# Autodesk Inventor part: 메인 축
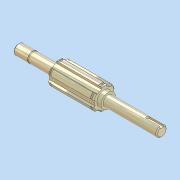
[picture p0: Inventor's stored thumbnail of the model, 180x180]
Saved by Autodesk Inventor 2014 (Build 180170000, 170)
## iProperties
Created: 2012-05
Part Number: 메인 축
Document SubType Name: 모델링
Designer: SeoGD™
Mass: 21.4462 g
Surface Area: 72.5109 cm^2
Volume: 21.4462 cm^3
Density: 1 g/cm^3
Material: 일반
Appearance: 기본값
변환 표준: STEP AP214IS
파일 이름: C:\Users\SeoGD\Desktop\?쒗뿕\硫붿씤 異?.stp
전처리기: Build: 253, Release: 2010 SP1 - Date: Wed 07/29/2009
전송 단위: 밀리미터
불확실성: 0.01
Author: SeoGD™
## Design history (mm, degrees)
sketch "스케치1"
  geometry: L1 (-69.5, 0)-(69.5, 0); L2 (69.5, 0)-(69.5, 5); L3 (69.5, 5)-(55.5, 5); L4 (55.5, 5)-(55.5, 4.8); L5 (55.5, 4.8)-(54.35, 4.8); L6 (54.35, 4.8)-(54.35, 5); L7 (54.35, 5)-(30.5, 5); L8 (30.5, 5)-(30.5, 9); L9 (30.5, 9)-(-13.5, 9); L10 (-13.5, 9)-(-13.5, 7); L11 (-13.5, 7)-(-17.5, 7); L12 (-17.5, 7)-(-17.5, 5); L13 (-17.5, 5)-(-69.5, 5); L14 (-69.5, 5)-(-69.5, 0); 2 further points
  constraints: 28 end point, 9 parallel, 4 collinear, 2 perpendicular, 1 coincident, 1 horizontal, 1 midpoint
  dimensions: "d2" = 1.15 distance between parallel lines of L6 L4; "d3" = 10 diameter of L3 L1; "d4" = 9.6 diameter of L5 L1; "d6" = 44 distance between parallel lines of L10 L8; "d7" = 4 distance between parallel lines of L12 L10; "d8" = 14 diameter of L11 L1; "d9" = 18 diameter of L9 L1; "d33" = 52 distance from line of L12.end L14; "d37" = 39 distance between parallel lines of L8 L2; "d38" = 14 distance between parallel lines of L2 L4
revolve "회전1" sketch "스케치1" stored, may be unused: angle "d10" = 90 deg
sketch "스케치2"
  geometry: L1 (2.5, 10.712)-(2.5, 8.646); L2 (-2.5, 10.712)-(-2.5, 8.646); A1 r 9 centre (0, 0) between (2.5, 8.646) and (-2.5, 8.646) reference; A2 r 11 centre (0, 0) between (2.5, 10.712) and (-2.5, 10.712); 1 further point
  constraints: 4 end point, 4 point on circle, 2 parallel, 1 centre point, 1 coincident, 1 vertical
  dimensions: "d11" = 22 diameter of A2; "d12" = 5 distance between parallel lines of L1 L2
extrude "돌출1" join sketch "스케치2" stored distance "d13" = 10; taper "d14" = 0 deg
chamfer "모따기1" distance "d15" = 1; stored, may be unused: second distance "d16" = 2, angle "d17" = 45 deg
node "작업 평면1"
node "작업 평면2"
sketch "스케치3"
  geometry: L1 (2.5, 10.712)-(2.5, 10.198); L2 (-2.5, 10.712)-(-2.5, 10.198); A1 r 11 centre (0, 0) between (2.5, 10.712) and (-2.5, 10.712) reference; A2 r 10.5 centre (0, 0) between (2.5, 10.198) and (-2.5, 10.198); 1 further point
  constraints: 4 end point, 2 point on circle, 1 centre point, 1 coincident, 1 parallel, 1 vertical
  dimensions: "d19" = 21 diameter of A2
extrude "돌출2" cut sketch "스케치3" distance "d20" = 1.35; taper "d21" = 0 deg
node "작업 평면3"
sketch "스케치4"
  geometry: L1 (-26, -5)-(-26, 5) reference; L2 (-26, 1.5)-(-12.5, 1.5); L3 (-12.5, -1.5)-(-26, -1.5); A1 r 1.5 centre (-12.5, 0) between (-12.5, -1.5) and (-12.5, 1.5); 2 further points
  constraints: 4 end point, 2 perpendicular, 2 point on circle, 2 point on line, 2 tangent, 1 centre point, 1 horizontal alignment, 1 midpoint
  dimensions: "d25" = 3 distance between parallel lines of L3 L2; "d26" = 15 dimension on A1 L1
extrude "돌출3" cut sketch "스케치4" distance "d27" = 1.8; taper "d28" = 0 deg
chamfer "모따기2" distance "d29" = 1; stored, may be unused: second distance "d30" = 2, angle "d31" = 45 deg
node "솔리드1"
node "솔리드 본체"
node "곡면 본체"
mirror "대칭1"
pattern_circular "원형 패턴1" dims "d23" = 360 deg
node "솔리드2"
other parameters: "d18" = -1.65
